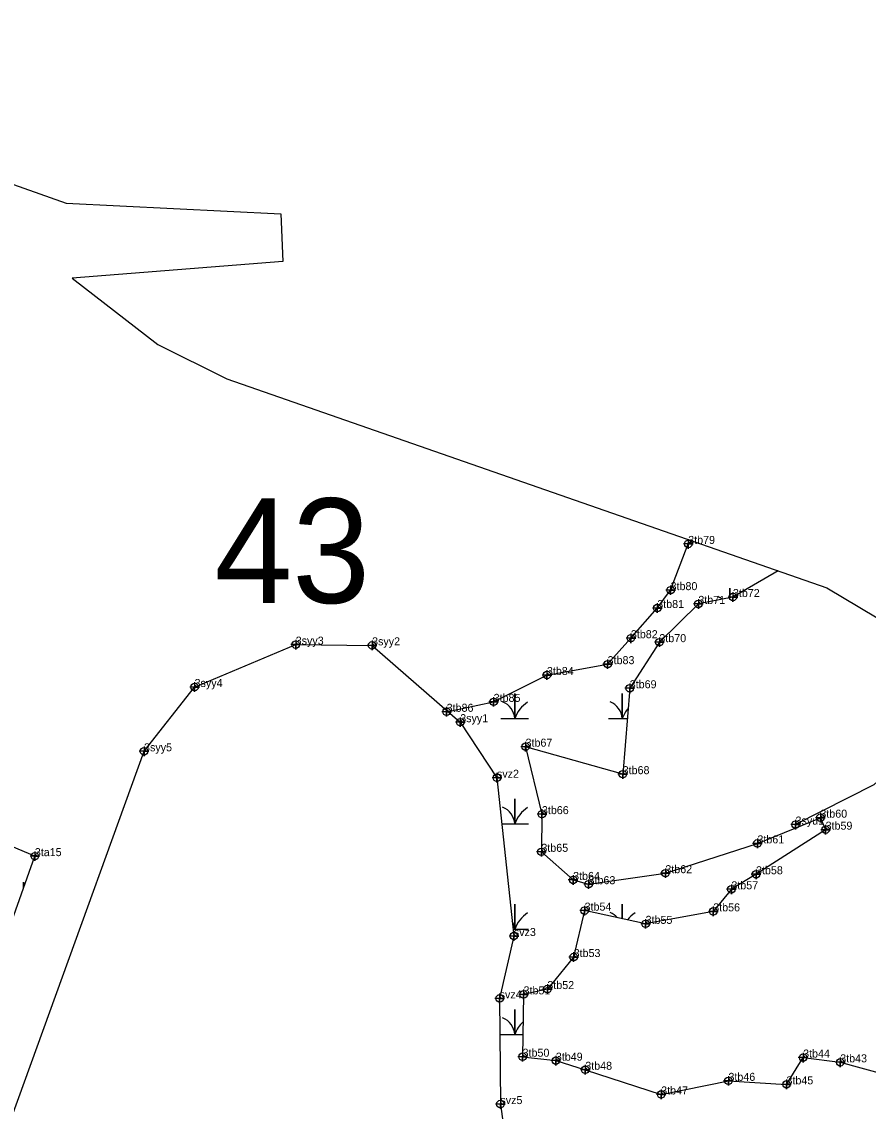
# Model space of a CAD drawing. Extents: x 2071991 to 2268989, y 436479 to 469629.
# Drawn here: x 2108547 to 2109076, y 455592 to 456273 of the extents above; entities that cross this region are included whole.
import ezdxf

# ---------------------------------------------------------------- set-up
doc = ezdxf.new("R2010")
doc.units = 0
for name, color, linetype in [('approx_PSA', 7, 'Continuous'), ('Default', 7, 'Continuous'), ('Exist Environmental Wetland Boundary', 7, 'Continuous'), ('Exist Environmental Wetland Boundary Cogo Comment', 7, 'Continuous'), ('Exist Environmental Wetland Boundary Cogo Point CELL', 7, 'Continuous'), ('Exist Hydro Jurisdictional Stream or Body of Water NEU Mitigable', 7, 'Continuous'), ('Exist Hydro Jurisdictional Stream or Body of Water NEU Mitigable Cogo Comment', 7, 'Continuous'), ('Exist Hydro Jurisdictional Stream or Body of Water NEU Mitigable Cogo Point CELL', 7, 'Continuous'), ('Exist Hydro Jurisdictional Stream or Body of Water NEU NonMitigable', 7, 'Continuous'), ('Exist Hydro Jurisdictional Stream or Body of Water NEU NonMitigable Cogo Comment', 7, 'Continuous'), ('Exist Hydro Jurisdictional Stream or Body of Water NEU NonMitigable Cogo Point CELL', 7, 'Continuous'), ('Exist Hydro Swamp or Marsh', 7, 'Continuous')]:
    doc.layers.add(name, color=color, linetype=linetype)

msp = doc.modelspace()

# ---------------------------------------------------------------- linework, layer by layer
at = {"layer": 'approx_PSA'}
for p, q in [((2108254.1, 456272.63), (2108574.42, 456159.35)), ((2108574.42, 456159.35), (2108708.62, 456152.76)), ((2108708.62, 456152.76), (2108709.83, 456122.89)), ((2108709.83, 456122.89), (2108578.32, 456112.47)), ((2108578.32, 456112.47), (2108631.84, 456071.1)), ((2108631.84, 456071.1), (2108674.76, 456049.66)), ((2108674.76, 456049.66), (2109049.66, 455919.13)), ((2109049.66, 455919.13), (2109250.2, 455799.97))]:
    msp.add_line(p, q, dxfattribs=at)
at = {"layer": 'Exist Environmental Wetland Boundary'}
for points in [[(2108327.68, 455612.12), (2108403.02, 455647.67), (2108435, 455660.53), (2108466.03, 455639), (2108489.79, 455618.8), (2108510.32, 455603.98), (2108516.98, 455609.72), (2108495.92, 455646.33), (2108516.51, 455644.08), (2108554.92, 455751.61), (2108520.56, 455766.03), (2108495.28, 455810.9), (2108465.54, 455859.89), (2108412.05, 455893.17), (2108366.35, 455921.19), (2108345.03, 455938.91), (2108323.73, 455982.26), (2108309.59, 456042.85)], [(2108812.18, 455841.76), (2108841.55, 455847.95), (2108874.83, 455864.72), (2108912.76, 455871.49), (2108927.27, 455887.7), (2108943.75, 455906.55), (2108952.08, 455917.71), (2108963.09, 455946.57), (2108965.46, 455948.44)], [(2109019.26, 455929.71), (2108991.02, 455913.43), (2108969.42, 455909.13), (2108945.07, 455885.23), (2108926.57, 455856.45), (2108922.16, 455802.79), (2108861.48, 455819.97), (2108871.7, 455777.84), (2108871.36, 455754.31), (2108891.19, 455736.74), (2108900.84, 455734.09), (2108948.81, 455740.96), (2109006.32, 455759.57), (2109045.64, 455775.63), (2109048.91, 455768.14), (2109005.46, 455740.3), (2108990.06, 455730.9), (2108978.71, 455717.12), (2108936.47, 455709.33), (2108898.35, 455717.58), (2108891.52, 455688.59), (2108875.1, 455668.6), (2108860.23, 455665.28), (2108859.62, 455626.35), (2108880.4, 455623.89), (2108898.79, 455618.21), (2108946.19, 455602.8), (2108988.22, 455611.28), (2109024.48, 455609.11), (2109034.87, 455625.83), (2109058.05, 455622.85), (2109086.12, 455615.35)]]:
    msp.add_lwpolyline(points, dxfattribs=at)
at = {"layer": 'Exist Environmental Wetland Boundary Cogo Point CELL'}
for points in [[(2108963.09, 455949.57), (2108963.09, 455943.57), (2108963.09, 455946.57), (2108966.09, 455946.57), (2108960.09, 455946.57)], [(2108952.08, 455920.71), (2108952.08, 455914.71), (2108952.08, 455917.71), (2108955.08, 455917.71), (2108949.08, 455917.71)], [(2108991.02, 455916.43), (2108991.02, 455910.43), (2108991.02, 455913.43), (2108994.02, 455913.43), (2108988.02, 455913.43)], [(2108943.75, 455909.55), (2108943.75, 455903.55), (2108943.75, 455906.55), (2108946.75, 455906.55), (2108940.75, 455906.55)], [(2108969.42, 455912.13), (2108969.42, 455906.13), (2108969.42, 455909.13), (2108972.42, 455909.13), (2108966.42, 455909.13)], [(2108927.27, 455890.7), (2108927.27, 455884.7), (2108927.27, 455887.7), (2108930.27, 455887.7), (2108924.27, 455887.7)], [(2108945.07, 455888.23), (2108945.07, 455882.23), (2108945.07, 455885.23), (2108948.07, 455885.23), (2108942.07, 455885.23)], [(2108912.76, 455874.49), (2108912.76, 455868.49), (2108912.76, 455871.49), (2108915.76, 455871.49), (2108909.76, 455871.49)], [(2108874.83, 455867.72), (2108874.83, 455861.72), (2108874.83, 455864.72), (2108877.83, 455864.72), (2108871.83, 455864.72)], [(2108926.57, 455859.45), (2108926.57, 455853.45), (2108926.57, 455856.45), (2108929.57, 455856.45), (2108923.57, 455856.45)], [(2108812.18, 455844.76), (2108812.18, 455838.76), (2108812.18, 455841.76), (2108815.18, 455841.76), (2108809.18, 455841.76)], [(2108841.55, 455850.95), (2108841.55, 455844.95), (2108841.55, 455847.95), (2108844.55, 455847.95), (2108838.55, 455847.95)], [(2108861.48, 455822.97), (2108861.48, 455816.97), (2108861.48, 455819.97), (2108864.48, 455819.97), (2108858.48, 455819.97)], [(2108922.16, 455805.79), (2108922.16, 455799.79), (2108922.16, 455802.79), (2108925.16, 455802.79), (2108919.16, 455802.79)], [(2108871.7, 455780.84), (2108871.7, 455774.84), (2108871.7, 455777.84), (2108874.7, 455777.84), (2108868.7, 455777.84)], [(2109045.64, 455778.63), (2109045.64, 455772.63), (2109045.64, 455775.63), (2109048.64, 455775.63), (2109042.64, 455775.63)], [(2109048.91, 455771.14), (2109048.91, 455765.14), (2109048.91, 455768.14), (2109051.91, 455768.14), (2109045.91, 455768.14)], [(2108871.36, 455757.31), (2108871.36, 455751.31), (2108871.36, 455754.31), (2108874.36, 455754.31), (2108868.36, 455754.31)], [(2109006.32, 455762.57), (2109006.32, 455756.57), (2109006.32, 455759.57), (2109009.32, 455759.57), (2109003.32, 455759.57)], [(2108554.92, 455754.61), (2108554.92, 455748.61), (2108554.92, 455751.61), (2108557.92, 455751.61), (2108551.92, 455751.61)], [(2108948.81, 455743.96), (2108948.81, 455737.96), (2108948.81, 455740.96), (2108951.81, 455740.96), (2108945.81, 455740.96)], [(2109005.46, 455743.3), (2109005.46, 455737.3), (2109005.46, 455740.3), (2109008.46, 455740.3), (2109002.46, 455740.3)], [(2108891.19, 455739.74), (2108891.19, 455733.74), (2108891.19, 455736.74), (2108894.19, 455736.74), (2108888.19, 455736.74)], [(2108900.84, 455737.09), (2108900.84, 455731.09), (2108900.84, 455734.09), (2108903.84, 455734.09), (2108897.84, 455734.09)], [(2108990.06, 455733.9), (2108990.06, 455727.9), (2108990.06, 455730.9), (2108993.06, 455730.9), (2108987.06, 455730.9)], [(2108898.35, 455720.58), (2108898.35, 455714.58), (2108898.35, 455717.58), (2108901.35, 455717.58), (2108895.35, 455717.58)], [(2108978.71, 455720.12), (2108978.71, 455714.12), (2108978.71, 455717.12), (2108981.71, 455717.12), (2108975.71, 455717.12)], [(2108936.47, 455712.33), (2108936.47, 455706.33), (2108936.47, 455709.33), (2108939.47, 455709.33), (2108933.47, 455709.33)], [(2108891.52, 455691.59), (2108891.52, 455685.59), (2108891.52, 455688.59), (2108894.52, 455688.59), (2108888.52, 455688.59)], [(2108860.23, 455668.28), (2108860.23, 455662.28), (2108860.23, 455665.28), (2108863.23, 455665.28), (2108857.23, 455665.28)], [(2108875.1, 455671.6), (2108875.1, 455665.6), (2108875.1, 455668.6), (2108878.1, 455668.6), (2108872.1, 455668.6)], [(2108859.62, 455629.35), (2108859.62, 455623.35), (2108859.62, 455626.35), (2108862.62, 455626.35), (2108856.62, 455626.35)], [(2109034.87, 455628.83), (2109034.87, 455622.83), (2109034.87, 455625.83), (2109037.87, 455625.83), (2109031.87, 455625.83)], [(2108880.4, 455626.89), (2108880.4, 455620.89), (2108880.4, 455623.89), (2108883.4, 455623.89), (2108877.4, 455623.89)], [(2108898.79, 455621.21), (2108898.79, 455615.21), (2108898.79, 455618.21), (2108901.79, 455618.21), (2108895.79, 455618.21)], [(2109058.05, 455625.85), (2109058.05, 455619.85), (2109058.05, 455622.85), (2109061.05, 455622.85), (2109055.05, 455622.85)], [(2108988.22, 455614.28), (2108988.22, 455608.28), (2108988.22, 455611.28), (2108991.22, 455611.28), (2108985.22, 455611.28)], [(2109024.48, 455612.11), (2109024.48, 455606.11), (2109024.48, 455609.11), (2109027.48, 455609.11), (2109021.48, 455609.11)], [(2108946.19, 455605.8), (2108946.19, 455599.8), (2108946.19, 455602.8), (2108949.19, 455602.8), (2108943.19, 455602.8)]]:
    msp.add_lwpolyline(points, dxfattribs=at)
for centre in [(2108963.09, 455946.57), (2108952.08, 455917.71), (2108991.02, 455913.43), (2108943.75, 455906.55), (2108969.42, 455909.13), (2108927.27, 455887.7), (2108945.07, 455885.23), (2108912.76, 455871.49), (2108874.83, 455864.72), (2108926.57, 455856.45), (2108841.55, 455847.95), (2108812.18, 455841.76), (2108861.48, 455819.97), (2108922.16, 455802.79), (2108871.7, 455777.84), (2109045.64, 455775.63), (2109048.91, 455768.14), (2108871.36, 455754.31), (2109006.32, 455759.57), (2108554.92, 455751.61), (2108948.81, 455740.96), (2109005.46, 455740.3), (2108891.19, 455736.74), (2108900.84, 455734.09), (2108990.06, 455730.9), (2108898.35, 455717.58), (2108978.71, 455717.12), (2108936.47, 455709.33), (2108891.52, 455688.59), (2108875.1, 455668.6), (2108860.23, 455665.28), (2108859.62, 455626.35), (2109034.87, 455625.83), (2108880.4, 455623.89), (2108898.79, 455618.21), (2109058.05, 455622.85), (2108988.22, 455611.28), (2109024.48, 455609.11), (2108946.19, 455602.8)]:
    msp.add_circle(centre, 2.34, dxfattribs=at)
at = {"layer": 'Exist Hydro Jurisdictional Stream or Body of Water NEU Mitigable'}
msp.add_lwpolyline([(2109165.58, 455850.25), (2109112.4, 455826.8), (2109079.01, 455796.06), (2109030.13, 455771.32)], dxfattribs=at)
at = {"layer": 'Exist Hydro Jurisdictional Stream or Body of Water NEU Mitigable Cogo Point CELL'}
msp.add_lwpolyline([(2109030.13, 455774.32), (2109030.13, 455768.32), (2109030.13, 455771.32), (2109033.13, 455771.32), (2109027.13, 455771.32)], dxfattribs=at)
msp.add_circle((2109030.13, 455771.32), 2.34, dxfattribs=at)
at = {"layer": 'Exist Hydro Jurisdictional Stream or Body of Water NEU NonMitigable'}
msp.add_lwpolyline([(2108623.15, 455817.07), (2108654.72, 455857.23), (2108717.88, 455883.69), (2108765.6, 455883.25), (2108820.67, 455835.26), (2108843.6, 455800.56), (2108854.17, 455701.73), (2108845.29, 455662.75), (2108845.75, 455596.78), (2108856.57, 455516.67), (2108757.06, 455553.02), (2108680.69, 455508.55), (2108685.74, 455466.67), (2108656.31, 455444.29), (2108630.56, 455441.61), (2108621.57, 455424.54), (2108567.18, 455450.99), (2108505.2, 455491.56)], close=True, dxfattribs=at)
at = {"layer": 'Exist Hydro Jurisdictional Stream or Body of Water NEU NonMitigable Cogo Point CELL'}
for points in [[(2108717.88, 455886.69), (2108717.88, 455880.69), (2108717.88, 455883.69), (2108720.88, 455883.69), (2108714.88, 455883.69)], [(2108765.6, 455886.25), (2108765.6, 455880.25), (2108765.6, 455883.25), (2108768.6, 455883.25), (2108762.6, 455883.25)], [(2108654.72, 455860.23), (2108654.72, 455854.23), (2108654.72, 455857.23), (2108657.72, 455857.23), (2108651.72, 455857.23)], [(2108820.67, 455838.26), (2108820.67, 455832.26), (2108820.67, 455835.26), (2108823.67, 455835.26), (2108817.67, 455835.26)], [(2108623.15, 455820.07), (2108623.15, 455814.07), (2108623.15, 455817.07), (2108626.15, 455817.07), (2108620.15, 455817.07)], [(2108843.6, 455803.56), (2108843.6, 455797.56), (2108843.6, 455800.56), (2108846.6, 455800.56), (2108840.6, 455800.56)], [(2108854.17, 455704.73), (2108854.17, 455698.73), (2108854.17, 455701.73), (2108857.17, 455701.73), (2108851.17, 455701.73)], [(2108845.29, 455665.75), (2108845.29, 455659.75), (2108845.29, 455662.75), (2108848.29, 455662.75), (2108842.29, 455662.75)], [(2108845.75, 455599.78), (2108845.75, 455593.78), (2108845.75, 455596.78), (2108848.75, 455596.78), (2108842.75, 455596.78)]]:
    msp.add_lwpolyline(points, dxfattribs=at)
for centre in [(2108717.88, 455883.69), (2108765.6, 455883.25), (2108654.72, 455857.23), (2108820.67, 455835.26), (2108623.15, 455817.07), (2108843.6, 455800.56), (2108854.17, 455701.73), (2108845.29, 455662.75), (2108845.75, 455596.78)]:
    msp.add_circle(centre, 2.34, dxfattribs=at)
at = {"layer": 'Exist Hydro Swamp or Marsh'}
for points in [[(2108989.13, 455913.06), (2108989.13, 455919.04), (2108989.13, 455913.06)], [(2108846.12, 455837.48), (2108854.72, 455837.48), (2108854.72, 455853.26), (2108854.72, 455837.48), (2108863.32, 455837.48)], [(2108913.32, 455837.48), (2108921.92, 455837.48), (2108921.92, 455853.26), (2108921.92, 455837.48), (2108925.01, 455837.48)], [(2108846.68, 455771.7), (2108854.72, 455771.7), (2108854.72, 455787.48), (2108854.72, 455771.7), (2108863.32, 455771.7)], [(2108547.87, 455731.88), (2108547.87, 455735.28), (2108547.87, 455731.88)], [(2108853.72, 455705.92), (2108854.72, 455705.92), (2108854.72, 455721.7), (2108854.72, 455705.92), (2108863.32, 455705.92)], [(2108921.92, 455712.48), (2108921.92, 455721.7), (2108921.92, 455712.48)], [(2108846.12, 455640.14), (2108854.72, 455640.14), (2108854.72, 455655.92), (2108854.72, 455640.14), (2108859.84, 455640.14)]]:
    msp.add_lwpolyline(points, dxfattribs=at)
for centre, radius, start, end in [((2108976.86, 455902.37), 12.3, 52.34955, 67.53497), ((2108842.45, 455836.59), 12.3, 4.14034, 67.53497), ((2108872.96, 455831.42), 19.22, 122.12745, 161.62219), ((2108909.66, 455836.59), 12.3, 4.14034, 67.53497), ((2108940.16, 455831.42), 19.22, 139.55192, 161.62219), ((2108842.45, 455770.81), 12.3, 4.14034, 67.53497), ((2108872.96, 455765.64), 19.22, 122.12745, 161.62219), ((2108872.96, 455699.86), 19.22, 122.12745, 161.62219), ((2108909.66, 455705.03), 12.3, 41.17694, 67.53497), ((2108940.16, 455699.86), 19.22, 122.12745, 141.62995), ((2108842.45, 455705.03), 12.3, 4.14034, 29.39296), ((2108842.45, 455639.25), 12.3, 4.14034, 67.53497), ((2108872.96, 455634.08), 19.22, 132.54173, 161.62219)]:
    msp.add_arc(centre, radius, start, end, dxfattribs=at)

# ---------------------------------------------------------------- texts
at = {"layer": 'Default'}
msp.add_text('43', height=65.34, dxfattribs=at).set_placement((2108667.16, 455909.68))
at = {"layer": 'Exist Environmental Wetland Boundary Cogo Comment'}
for s, p in [('3tb79', (2108963.09, 455946.57)), ('3tb80', (2108952.08, 455917.71)), ('3tb71', (2108969.42, 455909.13)), ('3tb72', (2108991.02, 455913.43)), ('3tb81', (2108943.75, 455906.55)), ('3tb82', (2108927.27, 455887.7)), ('3tb70', (2108945.07, 455885.23)), ('3tb83', (2108912.76, 455871.49)), ('3tb84', (2108874.83, 455864.72)), ('3tb69', (2108926.57, 455856.45)), ('3tb85', (2108841.55, 455847.95)), ('3tb86', (2108812.18, 455841.76)), ('3tb67', (2108861.48, 455819.97)), ('3tb68', (2108922.16, 455802.79)), ('3tb66', (2108871.7, 455777.84)), ('3tb60', (2109045.64, 455775.63)), ('3tb59', (2109048.91, 455768.14)), ('3tb61', (2109006.32, 455759.57)), ('3ta15', (2108554.92, 455751.61)), ('3tb65', (2108871.36, 455754.31)), ('3tb62', (2108948.81, 455740.96)), ('3tb58', (2109005.46, 455740.3)), ('3tb64', (2108891.19, 455736.74)), ('3tb63', (2108900.84, 455734.09)), ('3tb57', (2108990.06, 455730.9)), ('3tb54', (2108898.35, 455717.58)), ('3tb56', (2108978.71, 455717.12)), ('3tb55', (2108936.47, 455709.33)), ('3tb53', (2108891.52, 455688.59)), ('3tb51', (2108860.23, 455665.28)), ('3tb52', (2108875.1, 455668.6)), ('3tb50', (2108859.62, 455626.35)), ('3tb49', (2108880.4, 455623.89)), ('3tb44', (2109034.87, 455625.83)), ('3tb43', (2109058.05, 455622.85)), ('3tb48', (2108898.79, 455618.21)), ('3tb46', (2108988.22, 455611.28)), ('3tb45', (2109024.48, 455609.11)), ('3tb47', (2108946.19, 455602.8))]:
    msp.add_text(s, height=5, dxfattribs=at).set_placement(p)
at = {"layer": 'Exist Hydro Jurisdictional Stream or Body of Water NEU Mitigable Cogo Comment'}
msp.add_text('3syu1', height=5, dxfattribs=at).set_placement((2109030.13, 455771.32))
at = {"layer": 'Exist Hydro Jurisdictional Stream or Body of Water NEU NonMitigable Cogo Comment'}
for s, p in [('3syy3', (2108717.88, 455883.69)), ('3syy2', (2108765.6, 455883.25)), ('3syy4', (2108654.72, 455857.23)), ('3syy1', (2108820.67, 455835.26)), ('3syy5', (2108623.15, 455817.07)), ('svz2', (2108843.6, 455800.56)), ('svz3', (2108854.17, 455701.73)), ('svz4', (2108845.29, 455662.75)), ('svz5', (2108845.75, 455596.78))]:
    msp.add_text(s, height=5, dxfattribs=at).set_placement(p)

doc.saveas('drawing.dxf')
